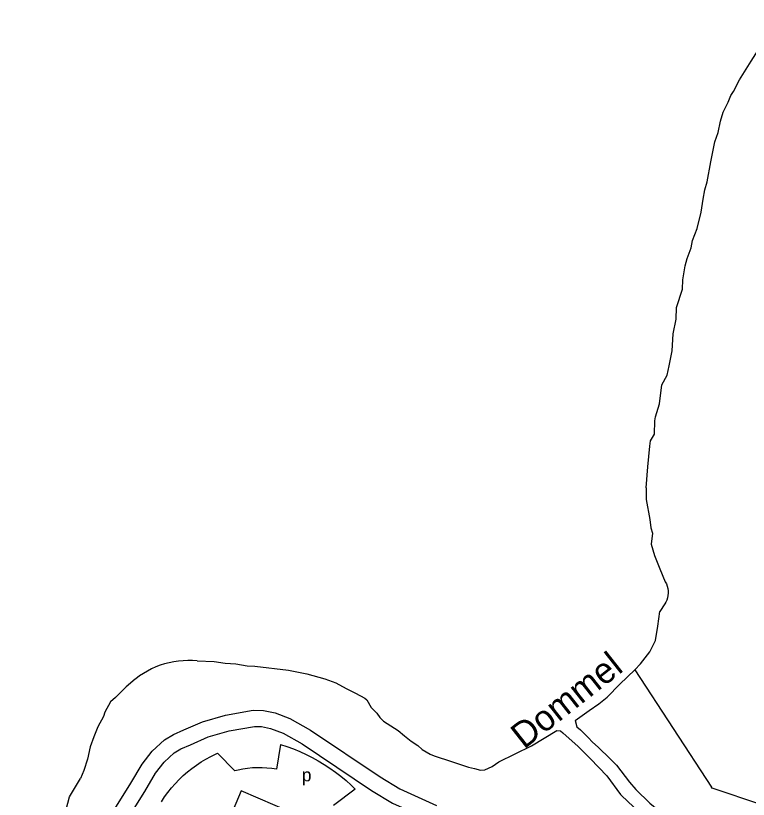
# Model space of a CAD drawing. Extents: x 162427 to 165104, y 384242 to 386287.
# Drawn here: x 162748.3 to 162975.8, y 385563.5 to 385807 of the extents above; entities that cross this region are included whole.
import ezdxf

# ---------------------------------------------------------------- set-up
doc = ezdxf.new("R2010")
doc.units = 0
for name, color, linetype in [('BLT_Basislijn', 7, 'Continuous'), ('BLT_Centroide', 7, 'Continuous'), ('BLT_Waternaam_spoorwegen', 7, 'Continuous')]:
    doc.layers.add(name, color=color, linetype=linetype)

msp = doc.modelspace()

# ---------------------------------------------------------------- linework, layer by layer
at = {"layer": 'BLT_Basislijn'}
for p, q in [((162949.93, 385624.23), (162948.38, 385621.91)), ((162940.55, 385603.8), (162964.39, 385567.3)), ((162830.56, 385580.62), (162829.35, 385572.86)), ((162816.43, 385572.35), (162811.02, 385577.85)), ((162853.74, 385566.74), (162846.99, 385561.61))]:
    msp.add_line(p, q, dxfattribs=at)
for points in [[(162967.19, 385774.18), (162968, 385777.03), (162969.52, 385780.12), (162970.38, 385782.22), (162971.21, 385783.41), (162973.07, 385787.02), (162976.73, 385792.87), (162978.92, 385796.24), (162982.82, 385801.61), (162986.73, 385806.97)], [(162958.08, 385734.86), (162958.51, 385737.08), (162959.93, 385740.83), (162961.2, 385745.91), (162961.84, 385750), (162962.29, 385752.85), (162963.03, 385755.38), (162964.2, 385761.57), (162965.38, 385767.76), (162966.44, 385770.7), (162967.19, 385774.18)], [(162951.68, 385700.28), (162952.16, 385702.81), (162952.51, 385708.18), (162953.37, 385712.67), (162953.52, 385716.35), (162955.42, 385721.99), (162955.46, 385724.88), (162956.21, 385729.29), (162956.78, 385731.55), (162958.08, 385734.86)], [(162944.14, 385660.34), (162944.66, 385666.79), (162945.19, 385673.25), (162945.42, 385674.89), (162946.73, 385676.93), (162946.77, 385681.11), (162946.97, 385682.38), (162948.27, 385686.42), (162948.97, 385692.3), (162950.58, 385695.3), (162951.26, 385698.22), (162951.68, 385700.28)], [(162944.14, 385660.34), (162944.09, 385656.63), (162945.28, 385650.49), (162945.57, 385647.85), (162946.06, 385646.17), (162945.66, 385642.81), (162946.15, 385641.03), (162946.65, 385639.25), (162948.34, 385635.18), (162950.04, 385631.11)], [(162950.04, 385631.11), (162950.37, 385630.45), (162950.62, 385629.77), (162950.8, 385629.06), (162950.91, 385628.33), (162950.93, 385627.6), (162950.87, 385626.87), (162950.74, 385626.15), (162950.52, 385625.45), (162950.24, 385624.78), (162949.93, 385624.23)], [(162940.55, 385603.8), (162942.37, 385605.58), (162945.24, 385609.38), (162947, 385612.86), (162947.69, 385617.38), (162948.38, 385621.91)], [(162804.66, 385606.53), (162803.21, 385606.64), (162801.76, 385606.67), (162800.31, 385606.61), (162798.86, 385606.48), (162797.43, 385606.27), (162796, 385605.98), (162794.6, 385605.62), (162793.21, 385605.17), (162791.86, 385604.65), (162790.53, 385604.06), (162789.24, 385603.4), (162787.99, 385602.66), (162786.77, 385601.86), (162785.61, 385600.99), (162785.43, 385600.84)], [(162804.66, 385606.53), (162810, 385606.32), (162813.35, 385605.79), (162816.66, 385605.66), (162820.23, 385605), (162822.63, 385604.88), (162833.06, 385603.68), (162838.75, 385602.55), (162844.31, 385600.94)], [(162929.43, 385593.23), (162931.96, 385595.28), (162935.93, 385599.29), (162940.55, 385603.8)], [(162785.43, 385600.84), (162782.63, 385598.48), (162779.29, 385595.18), (162777.81, 385593.85), (162776, 385590.62), (162775.57, 385589.25), (162773.84, 385586.1), (162772.65, 385582.96), (162771.46, 385579.81), (162770.62, 385575.98), (162769.49, 385572.51), (162768.45, 385570.01)], [(162844.31, 385600.94), (162847.72, 385599.7), (162850.93, 385598.01), (162853.84, 385596.51), (162856.74, 385595.01), (162857.41, 385594.42), (162858.71, 385592.07), (162860.44, 385590.28), (162861.43, 385588.92), (162862.5, 385587.85), (162867.06, 385584.91), (162869.11, 385583.23), (162871.15, 385581.56), (162873.2, 385580.21), (162874.5, 385579.01), (162877.07, 385577.59), (162878.31, 385577.02), (162883.63, 385575.26), (162888.94, 385573.51), (162890.81, 385573.08), (162892.68, 385572.64), (162894.02, 385572.73), (162896.26, 385573.72), (162898.31, 385575.21)], [(162762.24, 385533.6), (162784.14, 385568.6), (162787.62, 385574.47), (162790.7, 385578.49), (162794.53, 385582.03), (162797.38, 385583.67), (162800.56, 385585.08), (162806.36, 385587.66), (162813.54, 385589.73), (162822.1, 385591.19), (162825.26, 385591.13), (162828.91, 385590.37), (162833.47, 385588.66), (162839.9, 385585.06), (162861.53, 385570.51), (162867.64, 385566.79), (162879.02, 385561.65)], [(162922.1, 385587.98), (162926.39, 385591.14), (162929.43, 385593.23)], [(162761.2, 385522.51), (162766.48, 385530.94), (162788.41, 385566), (162791.77, 385571.66), (162794.41, 385575.12), (162797.5, 385577.98), (162799.64, 385579.2), (162802.6, 385580.51), (162808.08, 385582.95), (162814.65, 385584.84), (162822.48, 385586.18), (162824.7, 385586.14), (162827.51, 385585.55), (162831.36, 385584.11), (162837.28, 385580.8), (162858.83, 385566.3), (162865.3, 385562.36), (162877.09, 385557.03), (162888.31, 385552.73), (162896.96, 385550.32), (162905.89, 385548.44)], [(162922.1, 385587.98), (162922.54, 385586.04), (162923.76, 385585.16), (162926.09, 385582.79), (162927.4, 385581.27), (162929.16, 385579.75), (162932.92, 385576.17), (162934.92, 385574.11), (162938.91, 385568.91), (162940.88, 385566.6), (162945.28, 385562.36), (162948.62, 385559.54), (162949.98, 385558.93), (162952, 385558.44)], [(162898.31, 385575.21), (162908.46, 385580.15), (162916.4, 385584.93)], [(162916.4, 385584.93), (162917.45, 385584.86), (162918.26, 385584.17), (162922.97, 385580), (162926.8, 385576.15), (162931.92, 385570.8), (162936.11, 385565.09), (162938.57, 385562.64), (162944.56, 385557.26), (162950.46, 385551.47)], [(162830.56, 385580.62), (162832.58, 385579.96), (162834.58, 385579.21), (162836.55, 385578.4), (162838.49, 385577.51), (162840.39, 385576.54), (162842.25, 385575.51), (162844.08, 385574.41), (162845.86, 385573.24), (162847.6, 385572), (162849.29, 385570.7), (162850.93, 385569.34), (162852.51, 385567.92), (162853.74, 385566.74)], [(162793.61, 385562.8), (162794.57, 385564.27), (162795.6, 385565.7), (162796.69, 385567.08), (162797.85, 385568.4), (162799.06, 385569.68), (162800.33, 385570.9), (162801.65, 385572.06), (162803.02, 385573.15), (162804.45, 385574.19), (162805.92, 385575.16), (162807.43, 385576.06), (162808.98, 385576.89), (162810.57, 385577.65), (162811.02, 385577.85)], [(162829.35, 385572.86), (162827.86, 385573.1), (162826.36, 385573.27), (162824.86, 385573.36), (162823.35, 385573.36), (162821.84, 385573.29), (162820.34, 385573.14), (162818.85, 385572.9), (162817.38, 385572.59), (162816.43, 385572.35)], [(162748.34, 385529.7), (162749.22, 385531.46), (162750.95, 385533.33), (162753.46, 385539.52), (162754.22, 385542.33), (162755.54, 385544.39), (162756.71, 385547.34), (162757.35, 385548.6), (162762.11, 385555.44), (162763.5, 385558.42), (162765.1, 385564.33), (162768.45, 385570.01)], [(163116.12, 385462.98), (163064.49, 385534.84), (162980.05, 385561.82), (162964.58, 385567.01), (162964.39, 385567.3)], [(162836.46, 385535.85), (162844.79, 385554.75), (162818.33, 385566.15), (162812.27, 385551.72), (162801.8, 385556.33), (162796.54, 385544.37), (162805.66, 385540.36), (162811.36, 385541.63)]]:
    msp.add_lwpolyline(points, dxfattribs=at)

# ---------------------------------------------------------------- texts
at = {"layer": 'BLT_Centroide'}
msp.add_text('p', height=4, dxfattribs=at).set_placement((162837.2, 385569.13))
at = {"layer": 'BLT_Waternaam_spoorwegen'}
msp.add_text('Dommel', height=8, rotation=38.2605, dxfattribs=at).set_placement((162906.16, 385578.94))

doc.saveas('drawing.dxf')
